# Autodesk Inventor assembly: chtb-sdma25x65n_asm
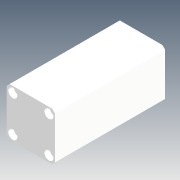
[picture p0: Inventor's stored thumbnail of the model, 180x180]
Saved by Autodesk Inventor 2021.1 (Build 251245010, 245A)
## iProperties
Company: Microsoft
Created: 2018-05
Part Number: chtb-sdma25x65n_asm
Description: STEP AP214
Document SubType Name: Assembly
Designer: user
Title: chtb-sdma25x65n_asm.STEP
Author: Windows
Revision Number: ÈÎºÎ
Sending System: SolidWorks 2015
Preprocessor: SwSTEP 2.0
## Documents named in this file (4)
- D:\Vault_2016\Projekty\Clamptek\Hydraulic\CHTB\CHTB-25\Inventor\chtb-sdma25x65n\chtb-sdma25x65n_asm.iam
- D:\Vault_2016\Projekty\Clamptek\Hydraulic\CHTB\CHTB-25\Inventor\chtb-sdma25x65n\CHTB-25QG.ipt
- D:\Vault_2016\Projekty\Clamptek\Hydraulic\CHTB\CHTB-25\Inventor\chtb-sdma25x65n\CHTB-SDMA25X65NBT.ipt
- D:\Vault_2016\Projekty\Clamptek\Hydraulic\CHTB\CHTB-25\Inventor\chtb-sdma25x65n\CHTB-SDMA25X65NHSG.ipt
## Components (3 placed, 3 different names)
1. CHTB-25QG_1
2. CHTB-SDMA25X65NBT_2
3. CHTB-SDMA25X65NHSG_3
